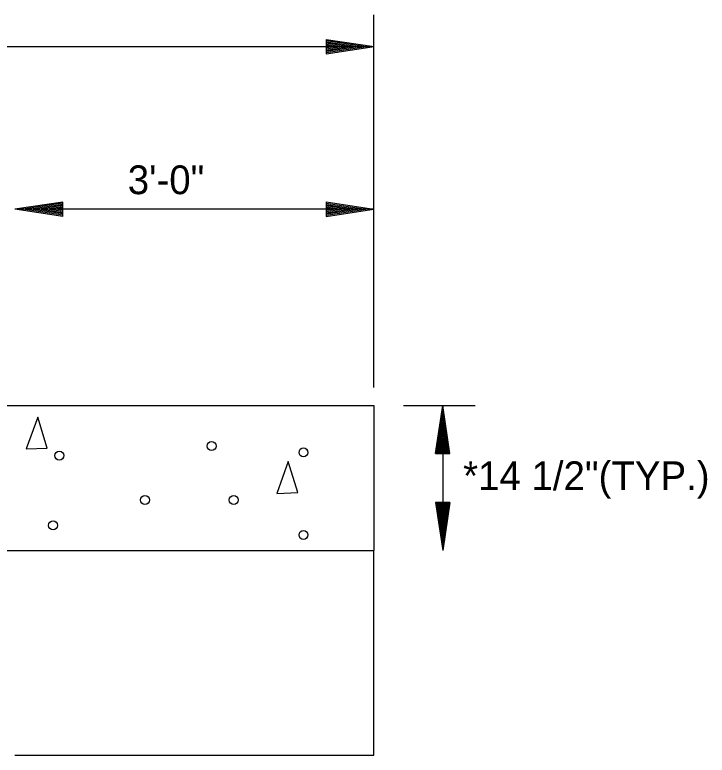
# Model space of a CAD drawing. Extents: x 3287 to 1767681, y -265 to 581440.
# Drawn here: x 3516.9 to 3545.81, y -239.71 to -208.81 of the extents above; entities that cross this region are included whole.
import ezdxf

# ---------------------------------------------------------------- set-up
doc = ezdxf.new("R2010")
doc.units = 0
doc.layers.add('Default', color=7, linetype='Continuous')

msp = doc.modelspace()

# ---------------------------------------------------------------- linework, layer by layer
at = {"layer": 'Default'}
for p, q in [((3531.893, -224.366), (3531.893, -208.806)), ((3529.896, -209.83), (3531.896, -210.13)), ((3529.896, -209.83), (3529.896, -210.43)), ((3529.896, -209.88), (3531.561, -210.13)), ((3529.896, -209.93), (3531.216, -210.13)), ((3529.896, -209.98), (3530.886, -210.13)), ((3529.896, -210.03), (3530.546, -210.13)), ((3529.896, -210.08), (3530.211, -210.13)), ((3449.399, -210.128), (3531.893, -210.128)), ((3529.896, -210.43), (3531.896, -210.13)), ((3529.896, -210.225), (3530.546, -210.13)), ((3529.896, -210.33), (3531.216, -210.13)), ((3529.896, -210.38), (3531.561, -210.13)), ((3529.896, -210.28), (3530.886, -210.13)), ((3529.896, -210.175), (3530.211, -210.13)), ((3531.893, -224.366), (3531.893, -215.841)), ((3531.893, -224.366), (3531.893, -215.841)), ((3531.893, -216.918), (3516.894, -216.918)), ((3518.897, -216.619), (3516.897, -216.919)), ((3518.897, -217.219), (3516.897, -216.919)), ((3518.897, -216.669), (3517.232, -216.919)), ((3518.897, -217.169), (3517.232, -216.919)), ((3518.897, -216.719), (3517.572, -216.919)), ((3518.897, -217.119), (3517.572, -216.919)), ((3518.897, -216.769), (3517.907, -216.919)), ((3518.897, -217.069), (3517.907, -216.919)), ((3518.897, -216.819), (3518.247, -216.919)), ((3518.897, -217.014), (3518.247, -216.919)), ((3518.897, -216.869), (3518.582, -216.919)), ((3518.897, -216.964), (3518.582, -216.919)), ((3518.897, -217.219), (3518.897, -216.619)), ((3529.893, -216.618), (3531.893, -216.918)), ((3529.893, -216.618), (3529.893, -217.218)), ((3529.893, -216.668), (3531.558, -216.918)), ((3529.893, -216.718), (3531.213, -216.918)), ((3529.893, -216.768), (3530.883, -216.918)), ((3529.893, -216.818), (3530.543, -216.918)), ((3529.893, -216.868), (3530.208, -216.918)), ((3529.893, -217.218), (3531.893, -216.918)), ((3529.893, -217.013), (3530.543, -216.918)), ((3529.893, -217.118), (3531.213, -216.918)), ((3529.893, -217.168), (3531.558, -216.918)), ((3529.893, -217.068), (3530.883, -216.918)), ((3529.893, -216.963), (3530.208, -216.918)), ((3349.405, -225.116), (3531.893, -225.116)), ((3531.893, -225.116), (3531.893, -231.157)), ((3533.129, -225.116), (3536.117, -225.116)), ((3534.466, -227.114), (3534.766, -225.114)), ((3535.066, -227.114), (3534.766, -225.114)), ((3534.768, -225.116), (3534.768, -231.157)), ((3534.516, -227.114), (3534.766, -225.444)), ((3535.016, -227.114), (3534.766, -225.444)), ((3534.571, -227.114), (3534.766, -225.789)), ((3534.966, -227.114), (3534.766, -225.789)), ((3534.621, -227.114), (3534.766, -226.124)), ((3534.916, -227.114), (3534.766, -226.124)), ((3534.671, -227.114), (3534.766, -226.464)), ((3534.866, -227.114), (3534.766, -226.464)), ((3534.721, -227.114), (3534.766, -226.794)), ((3534.816, -227.114), (3534.766, -226.794)), ((3534.466, -227.114), (3535.066, -227.114)), ((3534.466, -229.159), (3534.766, -231.159)), ((3535.066, -229.159), (3534.466, -229.159)), ((3534.516, -229.159), (3534.766, -230.824)), ((3534.571, -229.159), (3534.766, -230.479)), ((3534.621, -229.159), (3534.766, -230.149)), ((3534.671, -229.159), (3534.766, -229.809)), ((3534.721, -229.159), (3534.766, -229.474)), ((3535.066, -229.159), (3534.766, -231.159)), ((3534.866, -229.159), (3534.766, -229.809)), ((3534.966, -229.159), (3534.766, -230.479)), ((3535.016, -229.159), (3534.766, -230.824)), ((3534.916, -229.159), (3534.766, -230.149)), ((3534.816, -229.159), (3534.766, -229.474)), ((3456.898, -231.157), (3524.394, -231.157)), ((3516.894, -231.157), (3531.893, -231.157)), ((3531.893, -239.707), (3531.893, -231.157)), ((3516.894, -239.707), (3531.893, -239.707))]:
    msp.add_line(p, q, dxfattribs=at)
for points in [[(3517.857, -225.599), (3517.372, -226.924), (3518.252, -226.889), (3517.857, -225.599)], [(3528.311, -227.449), (3527.831, -228.779), (3528.711, -228.744), (3528.311, -227.449)]]:
    msp.add_lwpolyline(points, dxfattribs=at)
for centre in [(3525.111, -226.805), (3518.758, -227.202), (3528.95, -227.07), (3522.332, -229.056), (3526.038, -229.056), (3518.494, -230.116), (3528.95, -230.513)]:
    msp.add_circle(centre, 0.187, dxfattribs=at)

# ---------------------------------------------------------------- texts
for s, p in [('3\'-0"', (3521.612, -216.292)), ('*14 1/2"(TYP.)', (3535.616, -228.644))]:
    msp.add_text(s, height=1.2, dxfattribs=at).set_placement(p)

doc.saveas('drawing.dxf')
